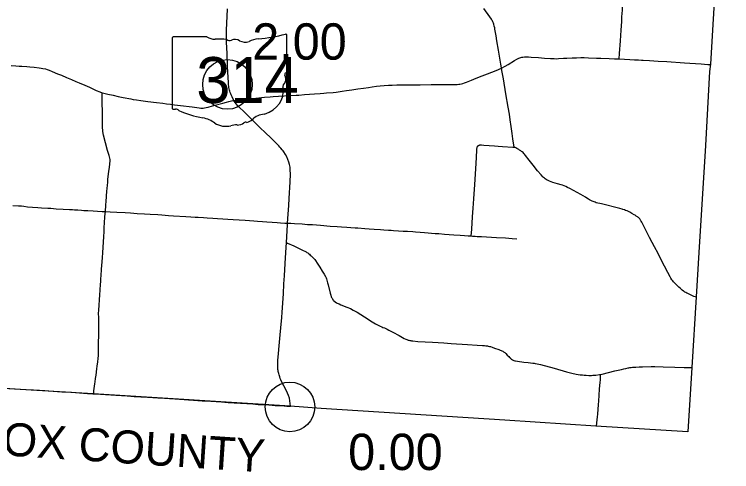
# Model space of a CAD drawing. Extents: x 1813937 to 1948437, y 826606 to 1022856.
# Drawn here: x 1907255 to 1928982, y 852982 to 866833 of the extents above; entities that cross this region are included whole.
import ezdxf

# ---------------------------------------------------------------- set-up
doc = ezdxf.new("R2010")
doc.units = 0
for name, color, linetype in [('Default', 7, 'Continuous'), ('GM_X_Adjacent_County_Text', 7, 'Continuous'), ('GM_X_County', 7, 'Continuous'), ('GM_X_County_Road', 7, 'Continuous'), ('GM_X_State_Route', 7, 'Continuous'), ('GM_X_State_Shield', 7, 'Continuous'), ('GM_X_Township_Road', 7, 'Continuous')]:
    doc.layers.add(name, color=color, linetype=linetype)

msp = doc.modelspace()

# ---------------------------------------------------------------- linework, layer by layer
at = {"layer": 'Default'}
for centre in [(1913710, 864711), (1915603, 854943)]:
    msp.add_circle(centre, 750, dxfattribs=at)
at = {"layer": 'GM_X_County'}
msp.add_lwpolyline([(1928987, 876105), (1928954, 875572), (1928932, 875213), (1928849, 873883), (1928341, 865325), (1928314, 865105), (1928189, 862861), (1927988, 859624), (1927907, 858279), (1927777, 856135), (1927658, 854184), (1924873, 854361), (1922111, 854537), (1916549, 854893), (1915609, 854967), (1909640, 855342), (1905546, 855583)], dxfattribs=at)
at = {"layer": 'GM_X_County_Road'}
for points in [[(1925577, 865482), (1925590, 865650), (1925613, 866026), (1925635, 866353), (1925651, 866614), (1925660, 866761), (1925672, 866958), (1925687, 867219), (1925706, 867530), (1925716, 867693), (1925727, 867873), (1925743, 868135), (1925765, 868478), (1925780, 868739), (1925793, 868952), (1925813, 869262), (1925827, 869476)], [(1922010, 865208), (1922119, 865267), (1922208, 865315), (1922405, 865433), (1922477, 865473), (1922535, 865502), (1922565, 865515), (1922596, 865526), (1922628, 865534), (1922660, 865540), (1922710, 865545), (1922759, 865547), (1922825, 865545), (1922907, 865541), (1923136, 865524), (1923316, 865511), (1923496, 865498), (1923611, 865492), (1923682, 865490), (1923742, 865492), (1923890, 865501), (1923988, 865506), (1924147, 865514), (1924152, 865514), (1924284, 865520), (1924415, 865522), (1924514, 865522), (1924645, 865518), (1924891, 865509), (1925022, 865505), (1925268, 865495), (1925429, 865488), (1925577, 865482)], [(1925577, 865482), (1925894, 865465), (1926038, 865458), (1926161, 865452), (1926248, 865446), (1926301, 865444), (1926495, 865433), (1926757, 865417), (1927018, 865401), (1927555, 865366), (1927718, 865355), (1928054, 865333), (1928259, 865318), (1928358, 865310)], [(1920339, 864710), (1920454, 864709), (1920601, 864708), (1920666, 864710), (1920715, 864715), (1920747, 864720), (1920795, 864730), (1920842, 864743), (1920889, 864759), (1920950, 864782), (1921102, 864843), (1921240, 864897), (1921428, 864970), (1921591, 865034), (1921851, 865137), (1922006, 865206), (1922010, 865208)], [(1913907, 864224), (1913965, 864232), (1914021, 864238), (1914567, 864294), (1914828, 864323), (1915008, 864339), (1915090, 864346), (1915254, 864354), (1915614, 864373), (1915794, 864385), (1915876, 864390), (1916040, 864402), (1916351, 864423), (1916515, 864435), (1916629, 864444), (1916711, 864451), (1916907, 864469), (1917004, 864480), (1917183, 864504), (1917313, 864522), (1917476, 864546), (1917654, 864573), (1917833, 864599), (1917979, 864620), (1918093, 864635), (1918223, 864653), (1918337, 864666), (1918452, 864678), (1918583, 864687), (1918697, 864693), (1918845, 864697), (1919058, 864700), (1919190, 864700), (1919354, 864700), (1919551, 864703), (1919879, 864707), (1920043, 864711), (1920191, 864711), (1920339, 864710)], [(1907206, 861041), (1907376, 861036), (1907470, 861029), (1907546, 861019), (1907650, 861006), (1907804, 860992), (1907963, 860983), (1908077, 860976), (1908264, 860965), (1908355, 860959), (1908522, 860947), (1908732, 860932), (1908922, 860924), (1909017, 860919), (1909081, 860914), (1909176, 860908), (1909292, 860901), (1909358, 860897), (1909485, 860888), (1909639, 860879), (1909776, 860872), (1909916, 860863), (1910012, 860858)], [(1910012, 860858), (1910156, 860849), (1910364, 860840), (1910612, 860828), (1910776, 860818), (1910972, 860805), (1911201, 860789), (1911366, 860779), (1911605, 860766), (1911723, 860758), (1911923, 860745), (1912071, 860735), (1912453, 860712), (1912603, 860701), (1912736, 860694), (1912822, 860688), (1912986, 860680), (1913100, 860673), (1913264, 860663), (1913411, 860653), (1913886, 860622), (1914246, 860597), (1914508, 860579), (1914622, 860571), (1914770, 860562), (1914904, 860551), (1915061, 860538), (1915211, 860528), (1915321, 860518), (1915444, 860511), (1915533, 860508)], [(1915496, 859920), (1915526, 859907), (1915720, 859818), (1915883, 859740), (1915958, 859705), (1916005, 859683), (1916050, 859660), (1916069, 859649), (1916089, 859638), (1916116, 859622), (1916141, 859606), (1916167, 859587), (1916192, 859566), (1916217, 859544), (1916242, 859522), (1916283, 859480), (1916332, 859427), (1916353, 859403), (1916374, 859376), (1916431, 859295), (1916510, 859171), (1916579, 859059), (1916639, 858962), (1916678, 858889), (1916697, 858848), (1916710, 858818), (1916723, 858783), (1916734, 858744), (1916745, 858704), (1916760, 858640), (1916819, 858386), (1916829, 858353), (1916837, 858323), (1916855, 858277), (1916865, 858257), (1916877, 858234), (1916890, 858214), (1916906, 858191), (1916921, 858174), (1916937, 858158), (1916973, 858126), (1917013, 858099), (1917037, 858085), (1917059, 858075), (1917093, 858061), (1917146, 858039), (1917329, 857967), (1917434, 857921), (1917521, 857875), (1917634, 857808), (1917857, 857669), (1918095, 857523), (1918199, 857462), (1918259, 857429), (1918295, 857410), (1918336, 857390), (1918382, 857368), (1918421, 857351), (1918463, 857334), (1918507, 857315), (1918549, 857296), (1918603, 857268), (1918721, 857208), (1918908, 857105), (1919066, 857019), (1919110, 856995), (1919139, 856983), (1919161, 856973), (1919184, 856966), (1919207, 856960), (1919232, 856955), (1919263, 856950), (1919287, 856947), (1919324, 856942), (1919476, 856929), (1919918, 856902), (1920262, 856879), (1920490, 856865), (1920981, 856834), (1921276, 856817), (1921437, 856807), (1921499, 856802), (1921533, 856798), (1921557, 856795), (1921582, 856790), (1921608, 856784), (1921647, 856775), (1921678, 856768), (1921731, 856751), (1921803, 856727), (1921926, 856681), (1921967, 856666), (1922003, 856651), (1922024, 856641), (1922047, 856629), (1922067, 856615), (1922089, 856602), (1922110, 856586), (1922139, 856559), (1922186, 856512), (1922231, 856465), (1922255, 856442), (1922272, 856425), (1922287, 856411), (1922302, 856401), (1922316, 856390), (1922347, 856372), (1922368, 856361), (1922389, 856351), (1922412, 856342), (1922435, 856336), (1922499, 856324), (1922691, 856301), (1922818, 856287), (1922957, 856271), (1922997, 856266), (1923035, 856261), (1923095, 856250), (1923191, 856227), (1923602, 856114), (1923981, 856009), (1924139, 855967), (1924268, 855939), (1924334, 855928), (1924397, 855919), (1924462, 855912), (1924511, 855907), (1924578, 855902), (1924658, 855899), (1924740, 855899), (1924776, 855900), (1924815, 855902), (1924870, 855907), (1924983, 855923), (1925012, 855929)], [(1925012, 855929), (1925061, 855938), (1925443, 856031), (1925650, 856081), (1925712, 856094), (1925780, 856110), (1925843, 856122), (1925867, 856126), (1925899, 856132), (1925940, 856138), (1925979, 856143), (1926013, 856146), (1926082, 856151), (1926181, 856157), (1926279, 856161), (1926541, 856170), (1926654, 856169), (1926907, 856160), (1927262, 856148), (1927540, 856139), (1927711, 856134), (1927729, 856133), (1927751, 856132), (1927784, 856130)]]:
    msp.add_lwpolyline(points, dxfattribs=at)
at = {"layer": 'GM_X_State_Route'}
msp.add_lwpolyline([(1915617, 854964), (1915613, 855047), (1915603, 855128), (1915585, 855208), (1915561, 855287), (1915531, 855363), (1915489, 855453), (1915420, 855583), (1915351, 855713), (1915329, 855764), (1915310, 855807), (1915294, 855851), (1915282, 855888), (1915273, 855919), (1915262, 855958), (1915249, 856019), (1915245, 856044), (1915240, 856078), (1915237, 856114), (1915234, 856152), (1915232, 856217), (1915239, 856348), (1915260, 856559), (1915279, 856788), (1915309, 857131), (1915327, 857343), (1915353, 857652), (1915365, 857816), (1915404, 858372), (1915421, 858666), (1915435, 858912), (1915456, 859288), (1915476, 859615), (1915496, 859920), (1915507, 860090), (1915530, 860466), (1915533, 860508), (1915549, 860777), (1915564, 861039), (1915578, 861251), (1915606, 861759), (1915615, 861988), (1915614, 862119), (1915605, 862201), (1915589, 862281), (1915567, 862361), (1915539, 862438), (1915506, 862514), (1915467, 862586), (1915415, 862670), (1915394, 862700), (1915371, 862730), (1915331, 862777), (1915301, 862810), (1915266, 862847), (1915163, 862951), (1915022, 863088), (1914858, 863249), (1914692, 863408), (1914201, 863891), (1914076, 864015), (1914028, 864065), (1913974, 864126), (1913926, 864192), (1913907, 864224), (1913893, 864248), (1913848, 864336), (1913822, 864391), (1913809, 864425), (1913795, 864464), (1913783, 864502), (1913772, 864539), (1913763, 864582), (1913755, 864620), (1913749, 864662), (1913745, 864696), (1913740, 864760), (1913716, 865251), (1913699, 865644), (1913684, 865988), (1913681, 866151), (1913685, 866348), (1913693, 866577), (1913699, 866773), (1913710, 867002)], dxfattribs=at)
at = {"layer": 'GM_X_State_Shield'}
for p, q in [((1912031, 866111), (1912031, 863998)), ((1913085, 866148), (1912066, 866148)), ((1915512, 865095), (1915512, 866200)), ((1915512, 865095), (1915512, 865095))]:
    msp.add_line(p, q, dxfattribs=at)
for centre, major_axis, start_param, end_param in [((1912071, 866116), (40.3, 0), 1.712693, 3.28349), ((1913328, 866393), (391, 0), 4.042523, 4.731795), ((1913457, 864961), (1404, 0), 1.404758, 1.657858), ((1913776, 866127), (113, 0), 3.836095, 5.185415), ((1913942, 865883), (235, 0), 0.950623, 2.079405), ((1914743, 865502), (743, 0), 1.699011, 2.107814), ((1914272, 869029), (3691, 0), 4.814394, 5.042369), ((1915473, 866205), (38.7, 0), 6.141152, 7.989035), ((1914245, 866218), (282, 0), 4.081561, 5.145723), ((1915503, 865013), (60, 0), 1.883978, 3.671073), ((1915121, 864874), (360, 0), 5.934695, 6.695948), ((1915471, 865090), (41.5, 0), 5.05454, 6.418171), ((1915651, 864632), (262, 0), 2.387724, 3.262537), ((1914479, 864491), (923, 0), 5.101752, 6.440018), ((1912072, 863993), (40.7, 0), 3.00124, 4.508301), ((1912078, 864210), (310, 0), 4.665946, 4.897461), ((1912141, 863876), (112, 0), 0.519207, 1.627899), ((1913555, 865775), (2665, 0), 4.195997, 4.488961), ((1912760, 863049), (834, 0), 0.823519, 1.323587), ((1914868, 863405), (506, 0), 1.647645, 2.488434), ((1913662, 863866), (529, 0), 4.026481, 4.996735), ((1913968, 863135), (435, 0), 1.495662, 1.94098), ((1914006, 863707), (282, 0), 4.691044, 5.507374), ((1914261, 863503), (79.4, 0), 1.147584, 2.315152), ((1914228, 863793), (298, 0), 4.937069, 5.64225)]:
    msp.add_ellipse(centre, major_axis=major_axis, ratio=0.8, start_param=start_param, end_param=end_param, dxfattribs=at)
at = {"layer": 'GM_X_Township_Road'}
for points in [[(1922010, 865208), (1922009, 865215), (1921988, 865321), (1921920, 865751), (1921874, 866026), (1921846, 866187), (1921813, 866381), (1921805, 866420), (1921792, 866478), (1921774, 866538), (1921765, 866565), (1921757, 866587), (1921749, 866608), (1921734, 866637), (1921720, 866661), (1921706, 866683), (1921656, 866757), (1921478, 867013)], [(1907155, 865282), (1907302, 865272), (1907400, 865265), (1907482, 865260), (1907629, 865250), (1907727, 865242), (1907857, 865230), (1908004, 865216), (1908069, 865207), (1908118, 865198), (1908197, 865178), (1908244, 865163), (1908306, 865141), (1908397, 865104), (1908564, 865036), (1908685, 864987), (1908836, 864923), (1908986, 864858), (1909122, 864802), (1909213, 864763), (1909393, 864684), (1909527, 864624), (1909737, 864531), (1909844, 864484), (1909910, 864456)], [(1922392, 862807), (1922355, 863065), (1922333, 863228), (1922304, 863439), (1922277, 863634), (1922250, 863812), (1922214, 864022), (1922146, 864426), (1922067, 864878), (1922021, 865137), (1922010, 865208)], [(1909921, 863493), (1909921, 863590), (1909922, 863719), (1909921, 863913), (1909919, 864120), (1909912, 864312), (1909910, 864456)], [(1909910, 864456), (1909968, 864443), (1910088, 864417), (1910246, 864382), (1910400, 864349), (1910552, 864319), (1910778, 864273), (1910858, 864258), (1910955, 864242), (1911085, 864225), (1911296, 864197), (1911556, 864161), (1911751, 864138), (1911864, 864122), (1911985, 864108), (1912105, 864095), (1912197, 864083), (1912374, 864063), (1912548, 864042), (1912645, 864030), (1912856, 864000), (1912905, 863996), (1912937, 863995), (1912969, 863995), (1913018, 864000), (1913066, 864009), (1913129, 864025), (1913255, 864060), (1913572, 864145), (1913682, 864176), (1913752, 864194), (1913791, 864202), (1913837, 864212), (1913877, 864219), (1913907, 864224)], [(1910045, 861283), (1910049, 861340), (1910058, 861464), (1910068, 861570), (1910075, 861651), (1910083, 861753), (1910091, 861836), (1910099, 861907), (1910115, 862082), (1910132, 862197), (1910146, 862309), (1910154, 862398), (1910153, 862439), (1910146, 862482), (1910122, 862560), (1910078, 862713), (1909959, 863171), (1909932, 863283), (1909923, 863440), (1909922, 863456), (1909921, 863493)], [(1921094, 860120), (1921104, 860216), (1921112, 860330), (1921135, 860705), (1921152, 860966), (1921171, 861244), (1921201, 861684), (1921241, 862320), (1921263, 862713), (1921266, 862758), (1921267, 862772), (1921269, 862789), (1921271, 862800), (1921272, 862806), (1921274, 862813), (1921276, 862819), (1921279, 862826), (1921285, 862834), (1921290, 862841), (1921295, 862846), (1921300, 862851), (1921307, 862857), (1921313, 862861), (1921321, 862865), (1921328, 862868), (1921335, 862871), (1921343, 862874), (1921351, 862876), (1921358, 862877), (1921368, 862878), (1921376, 862879), (1921388, 862879), (1921409, 862878), (1921474, 862874), (1921799, 862849), (1921914, 862841), (1922045, 862833), (1922351, 862813), (1922364, 862812), (1922377, 862810), (1922392, 862807)], [(1927917, 858265), (1927841, 858291), (1927772, 858318), (1927735, 858334), (1927650, 858375), (1927621, 858390), (1927590, 858407), (1927565, 858422), (1927540, 858438), (1927523, 858451), (1927481, 858484), (1927431, 858527), (1927383, 858570), (1927318, 858631), (1927277, 858671), (1927248, 858701), (1927222, 858732), (1927199, 858761), (1927172, 858797), (1927143, 858843), (1927121, 858881), (1927050, 859011), (1926850, 859399), (1926753, 859589), (1926647, 859793), (1926578, 859922), (1926497, 860072), (1926420, 860216), (1926287, 860480), (1926258, 860538), (1926244, 860564), (1926232, 860584), (1926221, 860602), (1926206, 860623), (1926197, 860635), (1926187, 860647), (1926176, 860658), (1926160, 860675), (1926144, 860689), (1926127, 860703), (1926111, 860714), (1926094, 860725), (1926058, 860749), (1926032, 860765), (1925959, 860806), (1925897, 860838), (1925857, 860858), (1925813, 860879), (1925767, 860897), (1925733, 860910), (1925690, 860925), (1925665, 860933), (1925596, 860952), (1925038, 861090), (1924878, 861129), (1924845, 861140), (1924816, 861150), (1924783, 861163), (1924756, 861176), (1924713, 861198), (1924677, 861218), (1924649, 861235), (1924599, 861266), (1924557, 861291), (1924415, 861373), (1924085, 861556), (1924012, 861593), (1923955, 861619), (1923906, 861639), (1923859, 861656), (1923813, 861671), (1923702, 861703), (1923561, 861745), (1923469, 861778), (1923423, 861797), (1923397, 861811), (1923366, 861829), (1923336, 861849), (1923313, 861867), (1923285, 861890), (1923263, 861910), (1923208, 861970), (1923104, 862098), (1922971, 862264), (1922851, 862421), (1922739, 862562), (1922709, 862598), (1922685, 862623), (1922662, 862647), (1922637, 862669), (1922618, 862684), (1922598, 862699), (1922581, 862710), (1922558, 862724), (1922539, 862735), (1922520, 862745), (1922472, 862771), (1922440, 862787), (1922420, 862796), (1922407, 862801), (1922392, 862807)], [(1910012, 860858), (1910014, 860883), (1910026, 861029), (1910039, 861193), (1910045, 861283)], [(1909805, 856847), (1909805, 856849), (1909810, 857145), (1909813, 857342), (1909811, 857463), (1909811, 857571), (1909809, 857667), (1909807, 857752), (1909807, 857794), (1909809, 857855), (1909810, 857887), (1909819, 858017), (1909833, 858197), (1909843, 858328), (1909854, 858492), (1909864, 858655), (1909870, 858737), (1909878, 858835), (1909884, 858917), (1909898, 859114), (1909906, 859228), (1909922, 859457), (1909933, 859621), (1909943, 859769), (1909952, 859943), (1909961, 860092), (1909971, 860256), (1909979, 860385), (1909985, 860504), (1910000, 860707), (1910012, 860858)], [(1915533, 860508), (1915562, 860508), (1915627, 860506), (1915741, 860499), (1915970, 860484), (1916134, 860473), (1916281, 860463), (1916527, 860443), (1916822, 860422), (1917035, 860406), (1917166, 860396), (1917329, 860383), (1917444, 860376), (1917575, 860369), (1917657, 860364), (1917866, 860349), (1918006, 860340), (1918151, 860330), (1918347, 860316), (1918444, 860310), (1918591, 860299), (1918673, 860294), (1918739, 860289), (1918886, 860280), (1919033, 860271), (1919164, 860262), (1919327, 860251), (1919403, 860246), (1919547, 860236), (1919678, 860226), (1920005, 860200), (1920109, 860193), (1920283, 860178), (1920562, 860157), (1920758, 860142), (1920892, 860132), (1921004, 860124), (1921094, 860120)], [(1921094, 860120), (1921133, 860117), (1921215, 860112), (1921275, 860107), (1921332, 860103), (1921401, 860100), (1921858, 860078), (1922127, 860060), (1922335, 860045), (1922475, 860036)], [(1909702, 855702), (1909716, 855804), (1909728, 855902), (1909754, 856097), (1909764, 856178), (1909780, 856309), (1909791, 856407), (1909800, 856505), (1909804, 856587), (1909805, 856669), (1909804, 856718), (1909805, 856847)], [(1924892, 854363), (1924910, 854552), (1924919, 854646), (1924928, 854728), (1924951, 855019), (1924960, 855121), (1924964, 855169), (1924968, 855247), (1924971, 855299), (1924981, 855480), (1925001, 855692), (1925006, 855752), (1925010, 855823), (1925010, 855849), (1925011, 855905), (1925012, 855929)], [(1909654, 855341), (1909658, 855364), (1909667, 855429), (1909694, 855641), (1909702, 855702)], [(1905558, 855587), (1905695, 855578), (1905859, 855569), (1906104, 855555), (1906437, 855537), (1906585, 855530), (1906699, 855525), (1906856, 855514), (1906960, 855507), (1907282, 855488), (1907610, 855470), (1907839, 855457), (1908019, 855447), (1908182, 855436), (1908297, 855429), (1908559, 855411), (1908689, 855403), (1908804, 855396), (1908984, 855385), (1909229, 855370), (1909474, 855353), (1909637, 855341), (1909654, 855341)], [(1909654, 855341), (1909719, 855337), (1909866, 855329), (1910014, 855319), (1910178, 855310), (1910325, 855298), (1910497, 855288), (1910668, 855276), (1910887, 855260), (1911090, 855247), (1911290, 855235), (1911596, 855218), (1911807, 855205), (1911953, 855197), (1912117, 855186), (1912256, 855177), (1912403, 855167), (1912534, 855157), (1912681, 855148), (1912943, 855131), (1913205, 855114), (1913368, 855104), (1913532, 855092), (1913630, 855086), (1913728, 855080), (1913827, 855075), (1913908, 855070), (1914006, 855063), (1914105, 855057), (1914170, 855052), (1914301, 855044), (1914480, 855032), (1914639, 855021), (1914808, 855012), (1914961, 855002), (1915152, 854990), (1915266, 854983), (1915430, 854973), (1915512, 854968), (1915617, 854964)]]:
    msp.add_lwpolyline(points, dxfattribs=at)

# ---------------------------------------------------------------- texts
at = {"layer": 'Default'}
for s, p in [('2.00', (1914460, 865461)), ('0.00', (1917366, 853031))]:
    msp.add_text(s, height=1100, dxfattribs=at).set_placement(p)
at = {"layer": 'GM_X_Adjacent_County_Text'}
msp.add_text('KNOX COUNTY', height=1000, rotation=356.2231, dxfattribs=at).set_placement((1905024, 853603))
at = {"layer": 'GM_X_State_Shield'}
msp.add_text('314', height=1392.2, dxfattribs=at).set_placement((1912765, 864147))

doc.saveas('drawing.dxf')
